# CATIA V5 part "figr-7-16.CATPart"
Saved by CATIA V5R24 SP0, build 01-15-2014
Part number: Part2
Bounding box of the stored display mesh (mm): x -50 to 50, y -65 to 65, z 0 to 28
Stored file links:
  D:\KAVITA\CATIA V5-6R2014 Project_ Kavita\CATIA V5-6R2014_partfiles\Partfiles\c07_catia_v5-6r2014_prt\figr-7-16.CATPart
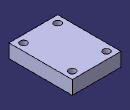
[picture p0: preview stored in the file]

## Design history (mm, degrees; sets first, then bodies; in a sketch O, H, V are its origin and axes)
Body1 (main body)
  Sketch1 on xy-plane, origin (0, 0, 0), H (1, 0, 0), V (0, 1, 0)
    line L1 (-50, 65) -> (50, 65)
    line L2 (50, 65) -> (50, -65)
    line L3 (50, -65) -> (-50, -65)
    line L4 (-50, -65) -> (-50, 65)
    axis line L5 (50, -65) -> (-50, 65)
    length L3 = 100
    length L2 = 130
    horizontal: L1 H, L3 H
    vertical: L2 V, L4 V
    midpoint: O L5
  Pad1: profile Sketch1, direction (0, 0, 1), length 28
  Sketch2 on face of Pad1, origin (25.9302, -33.7092, 28), H (1, 0, 0), V (0, 1, 0)
    point P1 (9.0698, -16.2908)
    reference projected line E1 (-75.9302, -31.2908) -> (24.0698, -31.2908) from edge [face of Pad1 | face of Pad1]
    reference projected line E2 (24.0698, -31.2908) -> (24.0698, 98.7092) from edge [face of Pad1 | face of Pad1]
    distance P1 E1 = 15
    distance P1 E2 = 15
  Hole1: placed by Sketch2, at (35, -50, 28) direction (0, 0, -1), diameter 14, through (limit type 3)
  RectPattern1: of Hole1, direction 1 instances 2, spacing 100, along edge [face of Pad1 | face of Pad1], direction 2 instances 2, spacing 70, along edge [face of Pad1 | face of Pad1]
